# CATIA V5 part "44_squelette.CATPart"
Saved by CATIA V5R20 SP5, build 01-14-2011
Part number: 44_squelette
Publications: "Plan.1", "Plan yz", "Plan.4", "Plan.5"
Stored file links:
  C:\Documents and Settings\anizard\Bureau\13\44_squelette.CATPart
  C:\Documents and Settings\anizard\Bureau\13\anizard.CATProduct
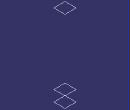
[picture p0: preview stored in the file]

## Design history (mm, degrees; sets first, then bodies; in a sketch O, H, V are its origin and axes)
Set1
  Plane1: linked copy from another document
Body1 (main body)
  Plane2: type Offset, RefPlane Plane1, Offset 8.5, reversed
  Plane3: type Offset, RefPlane Plane2, Offset 13, reversed
  Plane4: type Offset, RefPlane Plane3, Offset 2, reversed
